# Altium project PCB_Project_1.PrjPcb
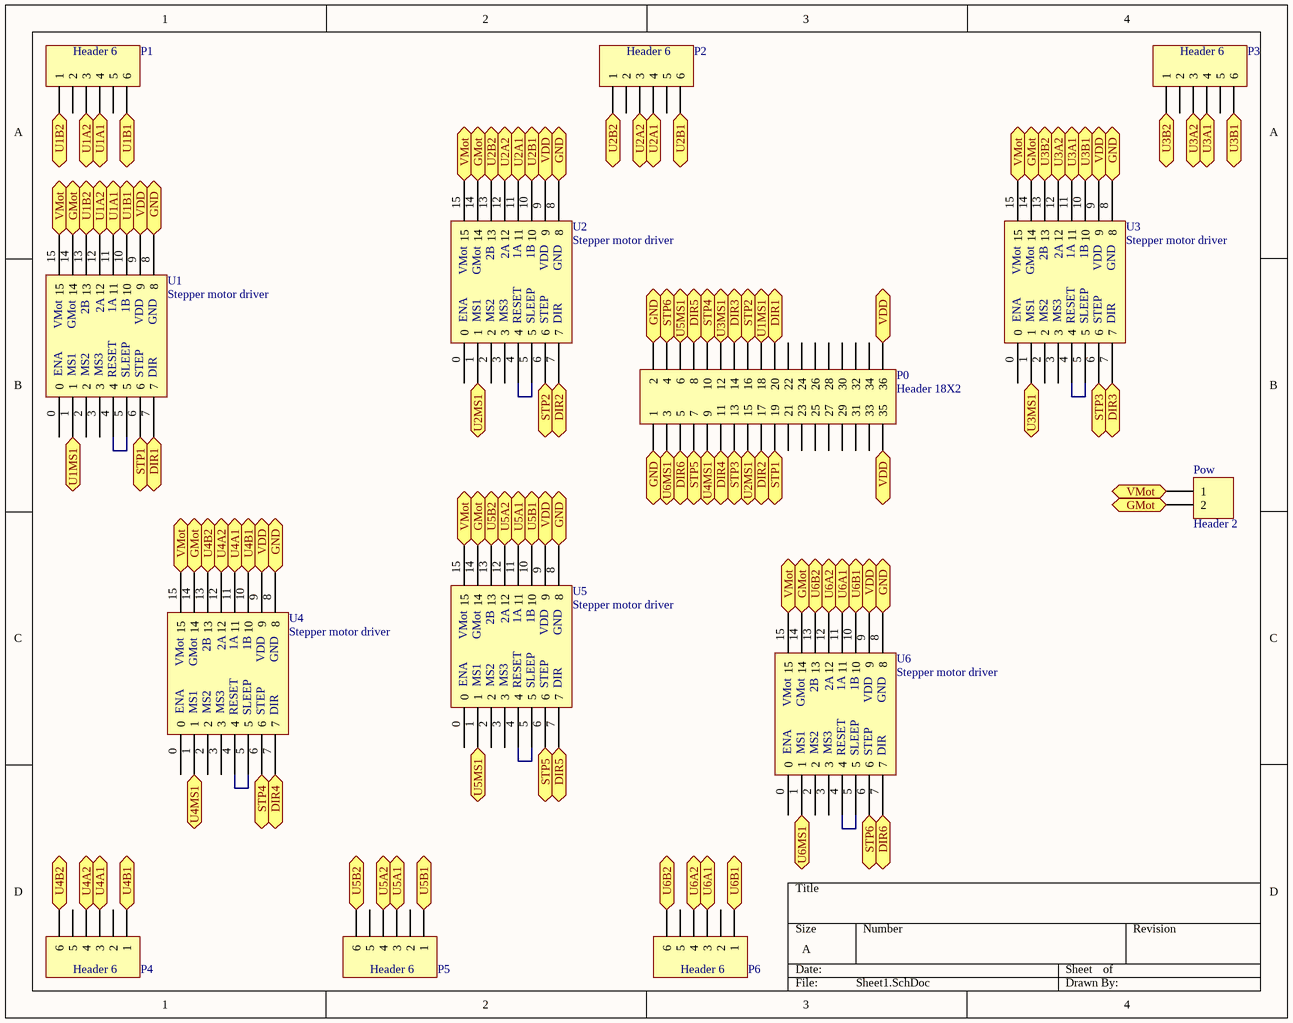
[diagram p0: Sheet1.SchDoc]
1 sheet, 14 parts. Net scope: flat (ports and power ports of the same name join across sheets).

## Sheet Sheet1.SchDoc
size A

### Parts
P0  Header 18X2  [HDR2X18]
P1  Header 6  [HDR1X6]
P2  Header 6  [HDR1X6]
P3  Header 6  [HDR1X6]
P4  Header 6  [HDR1X6]
P5  Header 6  [HDR1X6]
P6  Header 6  [HDR1X6]
Pow  Header 2  [HDR1X2]
U1  Stepper motor driver  [PCBDriver_1]
U2  Stepper motor driver  [PCBDriver_1]
U3  Stepper motor driver  [PCBDriver_1]
U4  Stepper motor driver  [PCBDriver_1]
U5  Stepper motor driver  [PCBDriver_1]
U6  Stepper motor driver  [PCBDriver_1]

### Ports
DIR1, DIR2, DIR3, DIR4, DIR5, DIR6, GMot, GND, STP1, STP2, STP3, STP4, STP5, STP6, U1A1, U1A2, U1B1, U1B2, U1MS1, U2A1, U2A2, U2B1, U2B2, U2MS1, U3A1, U3A2, U3B1, U3B2, U3MS1, U4A1, U4A2, U4B1, U4B2, U4MS1, U5A1, U5A2, U5B1, U5B2, U5MS1, U6A1, U6A2, U6B1, U6B2, U6MS1, VDD, VMot

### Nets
NetP0_1: P0.1 P0.2 U1.8 U2.8 U3.8 U4.8 U5.8 U6.8 ; port GND
NetP0_3: P0.3 U6.1 ; port U6MS1
NetP0_4: P0.4 U6.6 ; port STP6
NetP0_5: P0.5 U6.7 ; port DIR6
NetP0_6: P0.6 U5.1 ; port U5MS1
NetP0_7: P0.7 U5.6 ; port STP5
NetP0_8: P0.8 U5.7 ; port DIR5
NetP0_9: P0.9 U4.1 ; port U4MS1
NetP0_10: P0.10 U4.6 ; port STP4
NetP0_11: P0.11 U4.7 ; port DIR4
NetP0_12: P0.12 U3.1 ; port U3MS1
NetP0_13: P0.13 U3.6 ; port STP3
NetP0_14: P0.14 U3.7 ; port DIR3
NetP0_15: P0.15 U2.1 ; port U2MS1
NetP0_16: P0.16 U2.6 ; port STP2
NetP0_17: P0.17 U2.7 ; port DIR2
NetP0_18: P0.18 U1.1 ; port U1MS1
NetP0_19: P0.19 U1.6 ; port STP1
NetP0_20: P0.20 U1.7 ; port DIR1
NetP0_35: P0.35 P0.36 U1.9 U2.9 U3.9 U4.9 U5.9 U6.9 ; port VDD
NetP1_1: P1.1 U1.13 ; port U1B2
NetP1_3: P1.3 U1.12 ; port U1A2
NetP1_4: P1.4 U1.11 ; port U1A1
NetP1_6: P1.6 U1.10 ; port U1B1
NetP2_1: P2.1 U2.13 ; port U2B2
NetP2_3: P2.3 U2.12 ; port U2A2
NetP2_4: P2.4 U2.11 ; port U2A1
NetP2_6: P2.6 U2.10 ; port U2B1
NetP3_1: P3.1 U3.13 ; port U3B2
NetP3_3: P3.3 U3.12 ; port U3A2
NetP3_4: P3.4 U3.11 ; port U3A1
NetP3_6: P3.6 U3.10 ; port U3B1
NetP4_1: P4.1 U4.10 ; port U4B1
NetP4_3: P4.3 U4.11 ; port U4A1
NetP4_4: P4.4 U4.12 ; port U4A2
NetP4_6: P4.6 U4.13 ; port U4B2
NetP5_1: P5.1 U5.10 ; port U5B1
NetP5_3: P5.3 U5.11 ; port U5A1
NetP5_4: P5.4 U5.12 ; port U5A2
NetP5_6: P5.6 U5.13 ; port U5B2
NetP6_1: P6.1 U6.10 ; port U6B1
NetP6_3: P6.3 U6.11 ; port U6A1
NetP6_4: P6.4 U6.12 ; port U6A2
NetP6_6: P6.6 U6.13 ; port U6B2
NetPow_1: Pow.1 U1.15 U2.15 U3.15 U4.15 U5.15 U6.15 ; port VMot
NetPow_2: Pow.2 U1.14 U2.14 U3.14 U4.14 U5.14 U6.14 ; port GMot
NetU1_4: U1.4 U1.5
NetU2_4: U2.4 U2.5
NetU3_4: U3.4 U3.5
NetU4_4: U4.4 U4.5
NetU5_4: U5.4 U5.5
NetU6_4: U6.4 U6.5

Not connected (* = marked no-connect by the designer): P0 21 22 23 24 25 26 27 28 29 30 31 32 33 34; P1 2 5; P2 2 5; P3 2 5; P4 2 5; P5 2 5; P6 2 5; U1 0 2 3; U2 0 2 3; U3 0 2 3; U4 0 2 3; U5 0 2 3; U6 0 2 3

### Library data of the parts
P0 = Header 18X2: Header, 18-Pin, Dual row
P1-P6 = Header 6: Header, 6-Pin
Pow = Header 2: Header, 2-Pin
U1-U6 = Driver_1: Stepper Motor Driver module A4988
